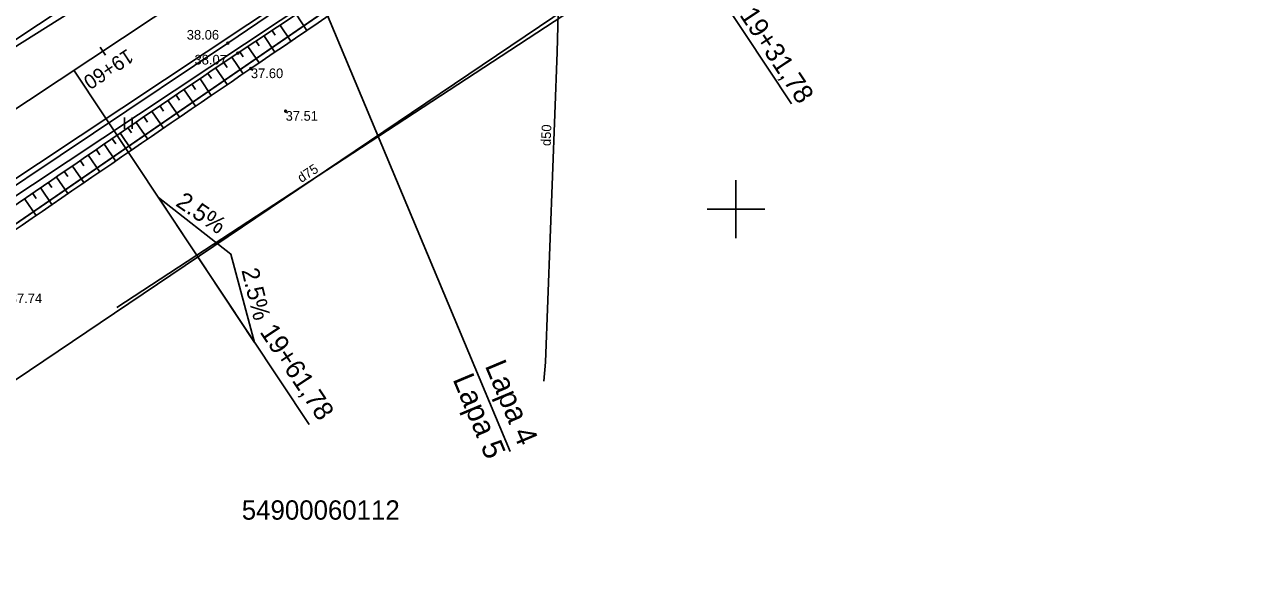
# Model space of a CAD drawing. Extents: x 469981 to 472086, y 246785 to 247785.
# Drawn here: x 470213.2 to 470276.9, y 246931.2 to 246959.6 of the extents above; entities that cross this region are included whole.
import ezdxf

# ---------------------------------------------------------------- set-up
doc = ezdxf.new("R2010")
doc.units = 0
for name, color, linetype in [('0_922', 7, 'Continuous'), ('0_Asfalta_mala', 7, 'Continuous'), ('0_Asfalta_Nomale', 7, 'Continuous'), ('0_Ruut_Braukt', 7, 'Continuous'), ('0_Ruut_nomale', 7, 'Continuous'), ('0_Saviet_Lin', 7, 'Continuous'), ('0_Virazjas', 7, 'Continuous'), ('21', 7, 'Continuous'), ('6_piketaza', 7, 'Continuous'), ('CELI_CMAL_####_####_#', 7, 'Continuous'), ('DREN_VADP_####_####_#', 7, 'Continuous'), ('DREN_VADP_####_TKST_#', 7, 'Continuous'), ('DREN_VADP_KLKT_####_#', 7, 'Continuous'), ('DREN_VADP_KLKT_TKST_#', 7, 'Continuous'), ('GEOD_ELEM_####_####_#', 7, 'Continuous'), ('RAMI_UZMR_####_####_#', 7, 'Continuous'), ('RELJ_AATZ_####_TKST_#', 7, 'Continuous'), ('RELJ_ELEM_####_####_#', 7, 'Continuous'), ('RELJ_NOGA_####_####_#', 7, 'Continuous'), ('RELJ_NOGL_####_####_#', 7, 'Continuous'), ('ROBZ_IERR_####_####_#', 7, 'Continuous'), ('ROBZ_IERR_####_TKST_#', 7, 'Continuous'), ('ROBZ_PROJ_####_####_#', 7, 'Continuous'), ('TERT_ELEM_####_####_#', 7, 'Continuous')]:
    doc.layers.add(name, color=color, linetype=linetype)

msp = doc.modelspace()

# ---------------------------------------------------------------- linework, layer by layer
at = {"layer": '0_922'}
msp.add_line((470240.713, 246973.784), (470183.883, 246936.049), dxfattribs=at)
at = {"layer": '0_Asfalta_mala'}
for p, q in [((470182.224, 246938.548), (470239.053, 246976.283)), ((470185.543, 246933.55), (470242.372, 246971.284))]:
    msp.add_line(p, q, dxfattribs=at)
at = {"layer": '0_Asfalta_Nomale'}
msp.add_line((470185.958, 246932.925), (470242.787, 246970.66), dxfattribs=at)
at = {"layer": '0_Ruut_Braukt'}
for p, q in [((470239.053, 246976.283), (470182.224, 246938.548)), ((470185.543, 246933.55), (470242.372, 246971.284))]:
    msp.add_line(p, q, dxfattribs=at)
at = {"layer": '0_Ruut_nomale'}
for p, q in [((470182.224, 246938.548), (470239.053, 246976.283)), ((470242.372, 246971.284), (470185.543, 246933.55)), ((470185.958, 246932.925), (470242.787, 246970.66))]:
    msp.add_line(p, q, dxfattribs=at)
at = {"layer": '0_Saviet_Lin'}
msp.add_line((470214.658, 246993.962), (470238.309, 246937.454), dxfattribs=at)
at = {"layer": '0_Virazjas'}
for p, q in [((470252.882, 246955.456), (470240.713, 246973.784)), ((470227.89, 246938.861), (470215.72, 246957.189))]:
    msp.add_line(p, q, dxfattribs=at)
msp.add_lwpolyline([(470225.076, 246943.099), (470223.836, 246947.678), (470220.097, 246950.597)], close=True, dxfattribs=at)
at = {"layer": '21'}
msp.add_line((470240.713, 246973.784), (470146.15, 246910.994), dxfattribs=at)
at = {"layer": '6_piketaza'}
msp.add_lwpolyline([(470217.345, 246957.967), (470217.068, 246958.384)], dxfattribs=at)
at = {"layer": 'CELI_CMAL_####_####_#'}
for points in [[(470207.251, 246955.004), (470220.145, 246963.116), (470261.486, 246992.424), (470276.308, 247005.858), (470296.122, 247025.635), (470312.816, 247042.969), (470330.98, 247061.836), (470346.394, 247077.324), (470364.172, 247092.272), (470374.754, 247099.764), (470384.938, 247106.322), (470390.015, 247108.873), (470395.699, 247111.348), (470409.875, 247117.262), (470415.428, 247119.375), (470428.615, 247124.712), (470444.307, 247130.298), (470466.241, 247137.389), (470487.751, 247143.859), (470509.15, 247149.677), (470533.329, 247156.368), (470558.982, 247163.161), (470583.723, 247169.81), (470606.354, 247175.581)], [(470440.723, 247107.99), (470440.084, 247118.844), (470439.302, 247119.794), (470438.459, 247120.205), (470437.434, 247120.771), (470435.683, 247121.111), (470417.849, 247114.314), (470398.184, 247106.061), (470376.912, 247095.329), (470368.488, 247089.418), (470350.85, 247073.72), (470334.429, 247056.212), (470317.045, 247039.09), (470299.359, 247021.199), (470279.758, 247002.025), (470265.741, 246988.964), (470242.76, 246971.543), (470223.686, 246958.587), (470209.766, 246949.279)]]:
    msp.add_lwpolyline(points, dxfattribs=at)
at = {"layer": 'DREN_VADP_####_####_#'}
msp.add_lwpolyline([(470241.039, 246969.634), (470240.736, 246958.128), (470240.131, 246942.082), (470240.051, 246941.094)], dxfattribs=at)
at = {"layer": 'DREN_VADP_KLKT_####_#'}
msp.add_lwpolyline([(470355.84, 247029.317), (470356.44, 247045.884), (470357.293, 247069.467), (470322.272, 247033.825), (470311.427, 247022.787), (470278.296, 246989.068), (470265.457, 246976.001), (470248.264, 246964.754), (470217.931, 246944.913)], dxfattribs=at)
at = {"layer": 'GEOD_ELEM_####_####_#'}
for p, q in [((470250, 246951.5), (470250, 246950)), ((470248.5, 246950), (470250, 246950)), ((470250, 246950), (470250, 246948.5)), ((470250, 246950), (470251.5, 246950))]:
    msp.add_line(p, q, dxfattribs=at)
at = {"layer": 'RAMI_UZMR_####_####_#'}
msp.add_lwpolyline([(470682.857, 247179.693), (470601.924, 247155.957), (470538.749, 247139.954), (470448.7, 247112.965), (470443.256, 247108.572), (470439.042, 247107.166), (470426.399, 247105.409), (470390.93, 247093.141), (470379.516, 247082.95), (470369.859, 247080.841), (470357.567, 247068.014), (470285.914, 246993.254), (470269.057, 246978.845), (470246.406, 246963.908), (470178.978, 246918.441), (470154.395, 246901.045), (470104.604, 246871.942), (470081.833, 246858.073)], dxfattribs=at)
at = {"layer": 'RELJ_ELEM_####_####_#'}
for centre in [(470223.686, 246958.587), (470224.202, 246958.074), (470224.881, 246957.283), (470226.68, 246955.078)]:
    msp.add_circle(centre, 0.05, dxfattribs=at)
at = {"layer": 'RELJ_NOGA_####_####_#'}
for p, q in [((470227.221, 246960.095), (470227.779, 246959.25)), ((470225.971, 246959.265), (470226.142, 246959.008)), ((470226.387, 246959.542), (470226.955, 246958.69)), ((470225.14, 246958.708), (470225.313, 246958.451)), ((470225.556, 246958.987), (470226.129, 246958.13)), ((470224.312, 246958.148), (470224.486, 246957.891)), ((470224.726, 246958.429), (470225.306, 246957.571)), ((470223.072, 246957.305), (470223.656, 246956.449)), ((470223.485, 246957.586), (470223.66, 246957.329)), ((470223.898, 246957.867), (470224.481, 246957.01)), ((470222.246, 246956.741), (470222.829, 246955.886)), ((470222.659, 246957.023), (470222.834, 246956.766)), ((470221.42, 246956.177), (470222.004, 246955.324)), ((470221.833, 246956.459), (470222.008, 246956.203)), ((470220.595, 246955.612), (470221.178, 246954.761)), ((470221.007, 246955.894), (470221.182, 246955.639)), ((470219.358, 246954.764), (470219.532, 246954.509)), ((470219.77, 246955.046), (470220.352, 246954.198)), ((470220.182, 246955.329), (470220.357, 246955.074)), ((470218.533, 246954.198), (470218.707, 246953.944)), ((470218.945, 246954.481), (470219.526, 246953.635)), ((470217.708, 246953.632), (470217.882, 246953.379)), ((470218.121, 246953.915), (470218.7, 246953.071)), ((470216.884, 246953.067), (470217.057, 246952.814)), ((470217.296, 246953.349), (470217.874, 246952.507)), ((470215.647, 246952.218), (470216.222, 246951.379)), ((470216.059, 246952.501), (470216.232, 246952.249)), ((470216.472, 246952.784), (470217.048, 246951.943)), ((470214.821, 246951.654), (470215.396, 246950.814)), ((470215.234, 246951.936), (470215.407, 246951.684)), ((470213.996, 246951.089), (470214.57, 246950.249)), ((470214.409, 246951.371), (470214.581, 246951.119)), ((470213.17, 246950.526), (470213.744, 246949.684)), ((470213.583, 246950.807), (470213.755, 246950.555))]:
    msp.add_line(p, q, dxfattribs=at)
for points in [[(470120.845, 246890.769), (470123.591, 246892.466), (470150.351, 246909.177), (470171.26, 246922.106), (470191.149, 246935.734), (470210.204, 246948.514), (470224.202, 246958.074), (470243.113, 246970.411), (470266.522, 246987.913), (470280.536, 247001.251), (470299.823, 247020.383), (470317.592, 247038.544), (470334.877, 247055.828), (470351.425, 247073.192), (470366.151, 247085.967)], [(470191.297, 246946.326), (470199.076, 246951.08), (470206.775, 246955.957), (470212.93, 246960.227), (470219.069, 246964.52), (470221.779, 246966.326), (470230.031, 246971.567), (470235.51, 246975.093), (470238.207, 246976.92), (470240.857, 246978.815), (470250.613, 246986.265), (470260.213, 246993.913), (470261.356, 246994.83)]]:
    msp.add_spline(points, degree=3, dxfattribs=at)
at = {"layer": 'RELJ_NOGL_####_####_#'}
for points in [[(470122.047, 246889.925), (470124.645, 246891.606), (470151.263, 246908.028), (470171.623, 246921.498), (470191.873, 246934.822), (470224.882, 246957.282), (470243.432, 246969.856), (470267.182, 246986.981), (470282.015, 246999.84), (470300.677, 247018.663), (470318.825, 247036.845), (470336.227, 247054.122), (470352.943, 247071.373), (470367.141, 247084.447)], [(470260.657, 246995.044), (470259.659, 246994.389), (470254.708, 246990.877), (470249.918, 246987.138), (470245.145, 246983.372), (470240.25, 246979.781), (470234.784, 246976.183), (470229.231, 246972.715), (470223.673, 246969.252), (470218.195, 246965.673), (470215.126, 246963.517), (470212.091, 246961.309), (470205.961, 246956.98), (470198.279, 246952.125), (470190.54, 246947.358)]]:
    msp.add_spline(points, degree=3, dxfattribs=at)
at = {"layer": 'ROBZ_IERR_####_####_#'}
msp.add_lwpolyline([(470179.103, 246871.896), (470152.342, 246907.761), (470275.956, 246992.729), (470308.087, 246975.453)], dxfattribs=at)
at = {"layer": 'ROBZ_PROJ_####_####_#'}
msp.add_lwpolyline([(471398.351, 247372.094), (471346.741, 247338.478), (471133.176, 247205.05), (471108.425, 247194.786), (471087.339, 247189.709), (471023.306, 247181.157), (470962.604, 247185.245), (470905.63, 247205.857), (470878.75, 247214.454), (470852.344, 247217.039), (470815.743, 247215.147), (470778.583, 247209.26), (470718.669, 247194.633), (470636.973, 247175.147), (470468.364, 247124.23), (470431.624, 247112.202), (470396.219, 247097.502), (470371.503, 247083.47), (470275.956, 246992.729), (470152.342, 246907.761), (470066.737, 246851.23)], dxfattribs=at)
at = {"layer": 'TERT_ELEM_####_####_#'}
for p, q in [((470218.34, 246954.151), (470218.34, 246954.751)), ((470218.74, 246954.151), (470218.74, 246954.751))]:
    msp.add_line(p, q, dxfattribs=at)

# ---------------------------------------------------------------- texts
at = {"layer": '0_Saviet_Lin'}
for s, p in [('Lapa 4', (470236.983, 246941.896)), ('Lapa 5', (470235.314, 246941.197))]:
    msp.add_text(s, height=1.12, rotation=292.71116, dxfattribs=at).set_placement(p)
at = {"layer": '0_Virazjas'}
for s, height, rotation, p in [('19+31,78', 1, 303.58428, (470250.156, 246960.051)), ('2.5%', 0.899, 325.64608, (470220.939, 246950.21)), ('2.5%', 0.899, 284.00141, (470224.383, 246946.838)), ('19+61,78', 1, 303.58428, (470225.311, 246943.648))]:
    msp.add_text(s, height=height, rotation=rotation, dxfattribs=at).set_placement(p)
at = {"layer": '6_piketaza'}
msp.add_text('19+60', height=0.75, rotation=213.58428, dxfattribs=at).set_placement((470218.483, 246958.333))
at = {"layer": 'DREN_VADP_####_TKST_#'}
msp.add_text('d50', height=0.5, rotation=87.83901, dxfattribs=at).set_placement((470240.402, 246953.261))
at = {"layer": 'DREN_VADP_KLKT_TKST_#'}
msp.add_text('d75', height=0.5, rotation=33.18983, dxfattribs=at).set_placement((470227.495, 246951.348))
at = {"layer": 'RELJ_AATZ_####_TKST_#'}
for s, p in [('38.06', (470221.559, 246958.777)), ('38.07', (470221.964, 246957.489)), ('37.60', (470224.881, 246956.783)), ('37.51', (470226.68, 246954.578)), ('37.74', (470212.398, 246945.134))]:
    msp.add_text(s, height=0.5, dxfattribs=at).set_placement(p)
at = {"layer": 'ROBZ_IERR_####_TKST_#'}
msp.add_text('54900060112', height=1, dxfattribs=at).set_placement((470224.409, 246933.926))

doc.saveas('drawing.dxf')
